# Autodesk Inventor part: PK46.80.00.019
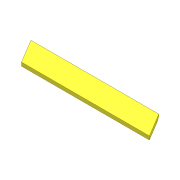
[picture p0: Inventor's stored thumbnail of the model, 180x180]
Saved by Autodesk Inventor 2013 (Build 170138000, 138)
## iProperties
Shininess: 64.0
Length Units: 11269
Angle Units: 11279
Time Units: 11290
Mass Units: 11283
Length Display Precision: 3
Angle Display Precision: 2
Compacted: True
Part Number: PK46.80.00.019
Document SubType Name: Modeling
Created: 2005-01
Material: Steel, Mild
Designer: SAlex
Manufacturer: Standard
Standards Organization: Custom
Density: 7.86 g/cm^3
Mass: 12177.1 g
Surface Area: 1953.57 cm^2
Volume: 1549.25 cm^3
Density: 0.0
Volumn: 0.0
Area: 0.0
PropertySet Name: Model Information
Control State: 0
Master: False
Checked Out: False
Checked Out Date: 2008-10-15
Last Check In Date: 2008-10-15
Author: SAlex
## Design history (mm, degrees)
derived "PK46.80.00.018.ipt"
body "Solid1"
tag "TaggingFeature4"
feature "DerivedBody::PK46.80.00.018.ipt" dims "d3" = 10
